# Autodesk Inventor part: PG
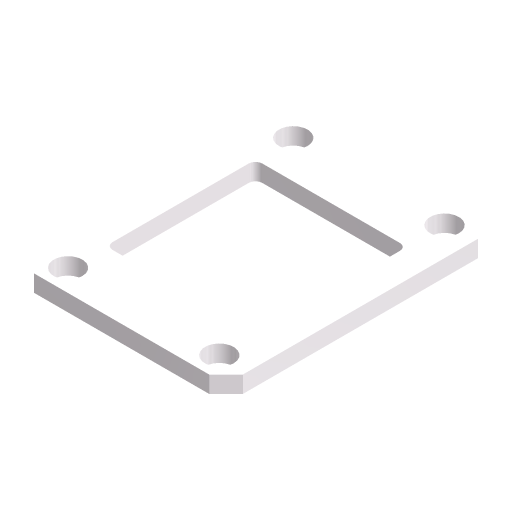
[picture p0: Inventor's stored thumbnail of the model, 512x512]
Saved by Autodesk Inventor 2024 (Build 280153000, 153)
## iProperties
Company: ATC
Shininess: 20.0
Length Units: 11269
Angle Units: 11279
Time Units: 11290
Mass Units: 11283
Length Display Precision: 3
Angle Display Precision: 2
Compacted: True
Created: 2023-03
Part Number: PG
Document SubType Name: Modeling
Designer: Andrzej Jaskulski
Material: Kurs-AJ
Density: 1 g/cm^3
Mass: 13.4822 g
Surface Area: 81.6818 cm^2
Volume: 13.4822 cm^3
Appearance: Kurs-AJ
Checked By: A.J.
Engr Approved By: Andrzej Jaskulski
Mfg Approved By: Andrzej Jaskulski
Authority: A.J.
Density: 0.0
Volumn: 0.0
Area: 0.0
PropertySet Name: Model Information
Control State: 0
Master: False
Checked Out: False
Title: A.J.: Kurs R2024-MEP
Author: Andrzej Jaskulski
Revision Number: 1/24
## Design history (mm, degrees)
sketch "Sketch1"
  geometry: L1 (37.5, -40)-(-24.672, -40) reference; L2 (-24.672, 40)-(37.5, 40) reference; L3 (37.5, -40)-(-24.672, -40); L4 (-24.672, -40)-(-24.672, 40); L5 (-24.672, 40)-(37.5, 40); L6 (37.5, 40)-(37.5, -40); L7 (37.5, -22.264)-(-32.672, -22.264) reference; L8 (-32.672, 22.264)-(37.5, 22.264) reference; L9 (27, -22.264)-(-14, -22.264); L10 (-16, -20.264)-(-16, 20.264); L11 (-14, 22.264)-(27, 22.264); L12 (29, 20.264)-(29, -20.264); C1 r 3.32 at (29, 33.5) reference; C2 r 3.32 at (29, -33.5) reference; C3 r 3.32 at (-16, -33.5) reference; C4 r 3.32 at (-16, 33.5) reference; C5 r 4.25 at (29, -33.5); C6 r 4.25 at (-16, -33.5); C7 r 4.25 at (29, 33.5); C8 r 4.25 at (-16, 33.5); A1 r 2 centre (27, -20.264) between (27, -22.264) and (29, -20.264); A2 r 2 centre (-14, -20.264) between (-16, -20.264) and (-14, -22.264); A3 r 2 centre (-14, 20.264) between (-14, 22.264) and (-16, 20.264); A4 r 2 centre (27, 20.264) between (29, 20.264) and (27, 22.264); 2 further points
  constraints: 16 end point, 8 centre point, 8 point on circle, 8 tangent, 6 point on line, 4 coincident, 4 parallel, 3 equal radius, 2 horizontal, 2 perpendicular
  dimensions: "d0" = 8.5 diameter of C5; "d1" = 8.5 diameter of C6 (= d0); "d2" = 8.5 diameter of C7 (= d0); "d3" = 8.5 diameter of C8 (= d0); "d4" = 2 radius of A1
extrude "Extrusion1" new body sketch "Sketch1" distance "d5" = 5; taper "d6" = 0 deg
chamfer "Chamfer1" distance "d7" = 5; stored, may be unused: second distance "d8" = 5, angle "d9" = 45 deg
node "Bryła1"
node "Korpusy bryłowe"
node "Korpusy powierzchniowe"
